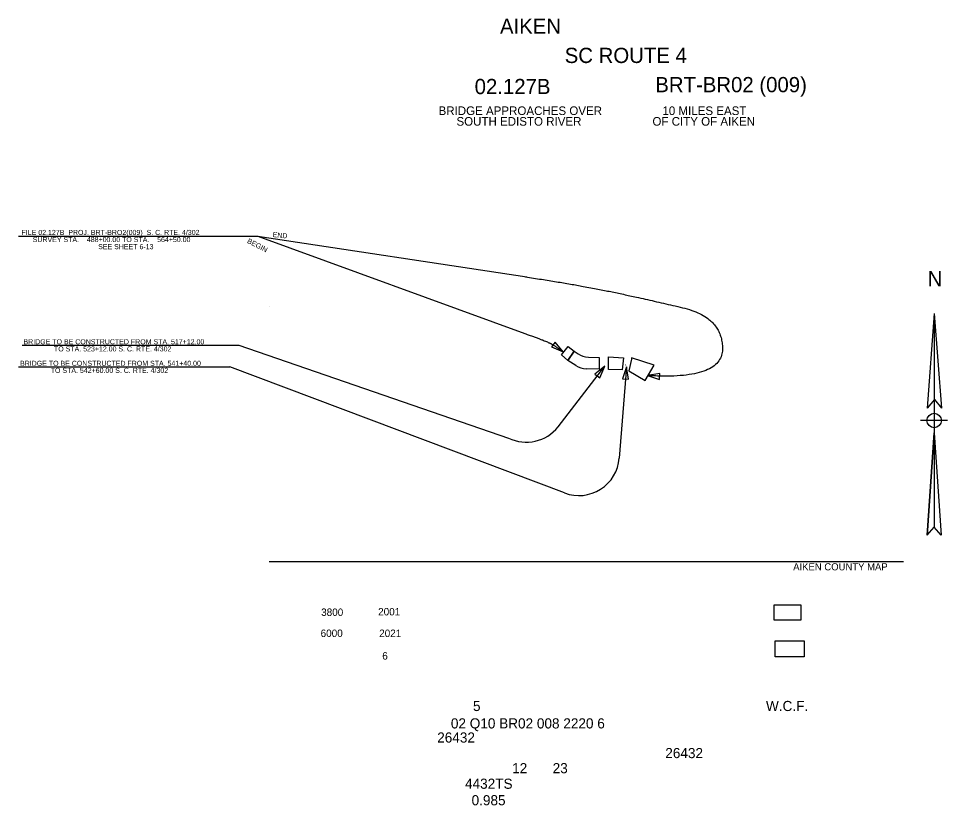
# Model space of a CAD drawing. Extents: x 17139 to 21295, y 12843 to 18076.
# Drawn here: x 20019 to 20935, y 14260 to 15036 of the extents above; entities that cross this region are included whole.
import ezdxf

# ---------------------------------------------------------------- set-up
doc = ezdxf.new("R2010")
doc.units = 0
for name, color, linetype in [('Level 1', 7, 'Continuous'), ('Level 10', 7, 'Continuous'), ('Level 24', 7, 'Continuous'), ('Level 3', 7, 'Continuous')]:
    doc.layers.add(name, color=color, linetype=linetype)

msp = doc.modelspace()

# ---------------------------------------------------------------- linework, layer by layer
at = {"layer": 'Level 1'}
for p, q in [((20266.41, 14751.65), (20266.41, 14751.65)), ((20266.41, 14751.65), (20266.41, 14751.65)), ((20554.29, 14704.19), (20560.97, 14712.44)), ((20566.73, 14707.66), (20560.81, 14698.58)), ((20566.73, 14707.66), (20560.81, 14698.58)), ((20560.97, 14712.44), (20566.73, 14707.66)), ((20560.81, 14698.58), (20554.29, 14704.19)), ((20891.41, 14500.04), (20266.41, 14500.04))]:
    msp.add_line(p, q, dxfattribs=at)
for points in [[(20518.88, 14780.95), (20570.73, 14773.09), (20633.69, 14759.96), (20712.91, 14741.33), (20713.17, 14679.12), (20639.2, 14683.58)], [(20518.2, 14725.03), (20537.46, 14718.27), (20547.43, 14713.55), (20556.08, 14706.99)]]:
    msp.add_open_spline(points, degree=2, dxfattribs=at)
at = {"layer": 'Level 10'}
for p, q in [((20921.51, 14744.77), (20914.56, 14651.47)), ((20921.51, 14744.77), (20928.76, 14651.47)), ((20921.51, 14744.77), (20921.51, 14534.07)), ((20921.86, 14660.02), (20914.56, 14651.47)), ((20921.86, 14660.02), (20928.76, 14651.47)), ((20908.26, 14639.67), (20934.66, 14639.67)), ((20921.71, 14627.07), (20914.61, 14526.22)), ((20914.61, 14526.22), (20921.71, 14627.07)), ((20921.71, 14627.07), (20928.61, 14526.22)), ((20914.61, 14526.22), (20921.56, 14534.27)), ((20928.61, 14526.22), (20921.56, 14534.27))]:
    msp.add_line(p, q, dxfattribs=at)
msp.add_circle((20921.61, 14639.37), 7.1, dxfattribs=at)
at = {"layer": 'Level 24'}
for p, q in [((20548.33, 14716.63), (20544.71, 14711.84)), ((20556.08, 14706.99), (20548.33, 14716.63)), ((20544.71, 14711.84), (20556.08, 14706.99)), ((20596.97, 14692.84), (20587.28, 14685.16)), ((20596.97, 14692.84), (20587.28, 14685.16)), ((20592.03, 14681.5), (20596.97, 14692.84)), ((20592.03, 14681.5), (20596.97, 14692.84)), ((20618.32, 14692.24), (20614.4, 14680.5)), ((20620.38, 14680.04), (20618.32, 14692.24)), ((20587.28, 14685.16), (20592.03, 14681.5)), ((20587.28, 14685.16), (20592.03, 14681.5)), ((20614.4, 14680.5), (20620.38, 14680.04)), ((20651.36, 14685.85), (20639.2, 14683.58)), ((20639.2, 14683.58), (20651, 14679.86)), ((20651, 14679.86), (20651.36, 14685.85))]:
    msp.add_line(p, q, dxfattribs=at)
at = {"layer": 'Level 3'}
for p, q in [((20019.48, 14821.03), (20255.1, 14821.03)), ((20255.1, 14821.03), (20520.16, 14780.95)), ((20255.1, 14821.03), (20518.2, 14725.03)), ((20023.05, 14713.57), (20236.51, 14713.57)), ((20236.51, 14713.57), (20502.25, 14622.08)), ((20560.81, 14698.58), (20566.73, 14707.66)), ((20566.73, 14707.66), (20570.71, 14705.06)), ((20568.48, 14693.58), (20560.81, 14698.58)), ((20580.89, 14701.82), (20591.44, 14701.43)), ((20600.82, 14689.59), (20600.82, 14701.96)), ((20600.82, 14701.96), (20615.62, 14701.12)), ((20615.62, 14701.12), (20614.02, 14689.33)), ((20623.36, 14699.86), (20620.67, 14688.41)), ((20623.53, 14701.12), (20623.36, 14699.86)), ((20645.71, 14693.85), (20623.53, 14701.12)), ((20019.46, 14692.15), (20227.69, 14692.15)), ((20557.38, 14567.93), (20227.69, 14692.15)), ((20551.1, 14633.15), (20596.97, 14692.84)), ((20591.44, 14689.86), (20578.66, 14690.34)), ((20614.02, 14689.33), (20600.82, 14689.59)), ((20618.32, 14692.24), (20611.36, 14602.28)), ((20617.95, 14694.17), (20617.42, 14694.02)), ((20636.99, 14678.89), (20645.71, 14693.85)), ((20620.67, 14688.41), (20636.99, 14678.89))]:
    msp.add_line(p, q, dxfattribs=at)
msp.add_lwpolyline([(20591.44, 14701.43), (20591.44, 14689.86)], dxfattribs=at)
for points in [[(20763.87, 14457.53), (20790.33, 14457.53), (20790.33, 14442.65), (20763.87, 14442.65)], [(20764.8, 14422.21), (20793.58, 14422.21), (20793.58, 14406.4), (20764.8, 14406.4)]]:
    msp.add_lwpolyline(points, close=True, dxfattribs=at)
for centre, radius, start, end in [((20581.64, 14721.81), 20, 236.87229, 267.85423), ((20579.41, 14710.33), 20, 236.87229, 267.85423), ((20519.78, 14658.03), 40, 244.00682, 321.53725), ((20571.48, 14605.37), 40, 249.35526, 355.57859)]:
    msp.add_arc(centre, radius, start, end, dxfattribs=at)

# ---------------------------------------------------------------- texts
at = {"layer": 'Level 1'}
for s, height, p in [('AIKEN', 15, (20493.79, 15020.57)), ('SC ROUTE 4', 15, (20557.57, 14991.76)), ('02.127B', 15, (20468.83, 14961.09)), ('BRT-BR02 (009)', 15, (20646.81, 14962.95)), ('BRIDGE APPROACHES OVER ', 8.5, (20433.28, 14940.48)), ('10 MILES EAST', 8.5, (20653.85, 14940.48)), ('SOUTH EDISTO RIVER', 8.5, (20450.91, 14929.98)), ('OF CITY OF AIKEN', 8.5, (20644.02, 14929.98)), ('3800', 7.327, (20317.57, 14446.71)), ('2001', 7.327, (20373.74, 14447.21)), ('6000', 7.327, (20317.07, 14425.95)), ('2021', 7.327, (20374.75, 14425.95)), ('6', 7.33, (20377.79, 14403.67)), ('5', 10, (20467.19, 14352.94)), ('W.C.F.', 10, (20755.88, 14352.94)), ('02 Q10 BR02 008 2220 6', 10, (20445.41, 14335.79)), ('26432', 10, (20431.95, 14321.85)), ('26432', 10, (20656.66, 14306.52)), ('12', 10, (20505.77, 14291.64)), ('23', 10, (20545.7, 14291.64)), ('4432TS', 10, (20459.34, 14276.31)), ('0.985', 10, (20465.84, 14260.04))]:
    msp.add_text(s, height=height, dxfattribs=at).set_placement(p)
at = {"layer": 'Level 10'}
msp.add_text('N', height=15, dxfattribs=at).set_placement((20915.16, 14771.62))
at = {"layer": 'Level 3'}
for s, height, p in [('FILE 02.127B  PROJ. BRT-BRO2(009)  S. C. RTE. 4/302', 5.0001, (20022.39, 14822.25)), ('SURVEY STA.    488+00.00 TO STA.    564+50.00', 5.0001, (20033.39, 14815.25)), ('SEE SHEET 6-13', 5.0001, (20097.9, 14808.24)), ('BRIDGE TO BE CONSTRUCTED FROM STA. 517+12.00', 5.0001, (20024.27, 14714.47)), ('TO STA. 523+12.00 S. C. RTE. 4/302', 5.0001, (20054.33, 14707.47)), ('BRIDGE TO BE CONSTRUCTED FROM STA. 541+40.00', 5.0001, (20020.88, 14693.25)), ('TO STA. 542+60.00 S. C. RTE. 4/302', 5.0001, (20051.14, 14686.25)), ('AIKEN COUNTY MAP', 7, (20782.69, 14491.64))]:
    msp.add_text(s, height=height, dxfattribs=at).set_placement(p)
for s, rotation, p in [('BEGIN', 332.69634, (20244.17, 14814.77)), ('END', 354.09019, (20269.62, 14820.26))]:
    msp.add_text(s, height=5, rotation=rotation, dxfattribs=at).set_placement(p)

doc.saveas('drawing.dxf')
